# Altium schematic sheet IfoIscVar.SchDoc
size A; DocumentNumber: 3; SheetNumber: 3; SheetTotal: 11; pInstance: Corner
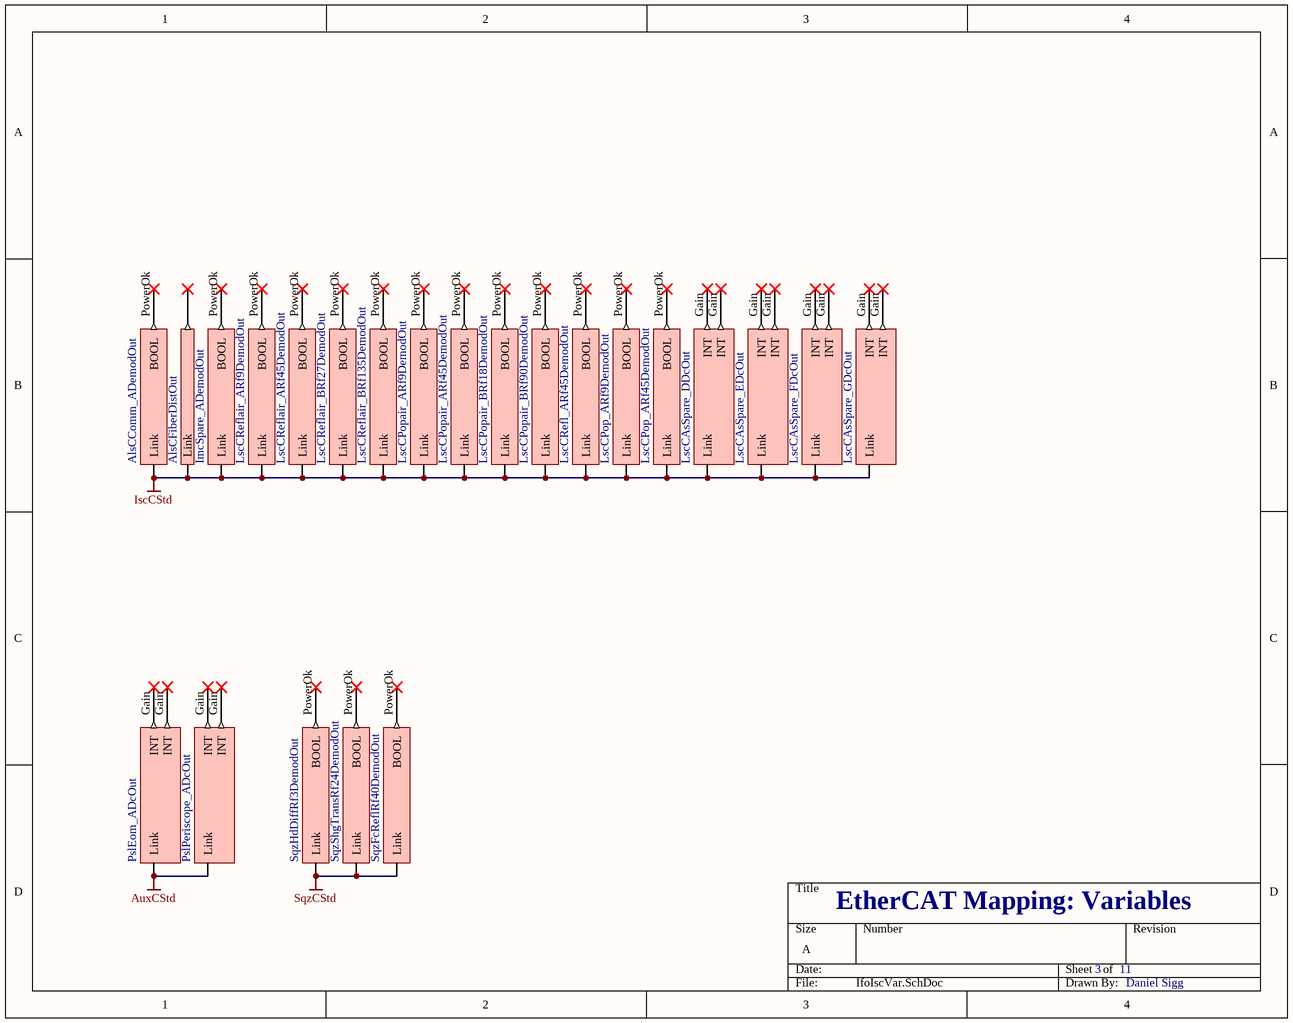
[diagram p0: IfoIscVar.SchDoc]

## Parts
V32  PslEom_ADcOut  (no BOM)
V33  PslPeriscope_ADcOut  (no BOM)
V34  AlsCComm_ADemodOut  (no BOM)
V35  AlsCFiberDistOut  (no BOM)
V36  ImcSpare_ADemodOut  (no BOM)
V37  LscCReflair_ARf9DemodOut  (no BOM)
V38  LscCReflair_ARf45DemodOut  (no BOM)
V39  LscCReflair_BRf27DemodOut  (no BOM)
V40  LscCReflair_BRf135DemodOut  (no BOM)
V41  LscCPopair_ARf9DemodOut  (no BOM)
V42  LscCPopair_ARf45DemodOut  (no BOM)
V43  LscCPopair_BRf18DemodOut  (no BOM)
V44  LscCPopair_BRf90DemodOut  (no BOM)
V45  LscCRefl_ARf45DemodOut  (no BOM)
V46  LscCPop_ARf9DemodOut  (no BOM)
V47  LscCPop_ARf45DemodOut  (no BOM)
V78  SqzHdDiffRf3DemodOut  (no BOM)
V79  SqzShgTransRf24DemodOut  (no BOM)
V80  SqzFcReflRf40DemodOut  (no BOM)
V740  LscCAsSpare_EDcOut  (no BOM)
V741  LscCAsSpare_FDcOut  (no BOM)
V742  LscCAsSpare_GDcOut  (no BOM)
V743  LscCAsSpare_DDcOut  (no BOM)

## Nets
AuxCStd: V32.0(Link) V33.0(Link)
IscCStd: V34.?1(Link) V35.?2(Link) V36.?1(Link) V37.?1(Link) V38.?1(Link) V39.?1(Link) V40.?1(Link) V41.?1(Link) V42.?1(Link) V43.?1(Link) V44.?1(Link) V45.?1(Link) V46.?1(Link) V47.?1(Link) V740.0(Link) V741.0(Link) V742.0(Link) V743.0(Link)
SqzCStd: V78.?1(Link) V79.?1(Link) V80.?1(Link)

Not connected (* = marked no-connect by the designer): V32 Gain(INT)*; V33 Gain(INT)*; V34 PowerOk(BOOL)*; V35 ?1*; V36 PowerOk(BOOL)*; V37 PowerOk(BOOL)*; V38 PowerOk(BOOL)*; V39 PowerOk(BOOL)*; V40 PowerOk(BOOL)*; V41 PowerOk(BOOL)*; V42 PowerOk(BOOL)*; V43 PowerOk(BOOL)*; V44 PowerOk(BOOL)*; V45 PowerOk(BOOL)*; V46 PowerOk(BOOL)*; V47 PowerOk(BOOL)*; V78 PowerOk(BOOL)*; V79 PowerOk(BOOL)*; V80 PowerOk(BOOL)*; V740 Gain(INT)*; V741 Gain(INT)*; V742 Gain(INT)*; V743 Gain(INT)*

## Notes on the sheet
- EtherCAT Mapping: Variables
- Daniel Sigg

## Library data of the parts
V32 V33 = DCPower_DCPowerOutStruct: DCPowerOutStruct; BoxType: Variable; Instance: H1AuxCorner Instance; PLC: H1AuxCorner; Task: AuxCStd
V34 V36-V47 = Demodulator_DemodulatorOutStruct: DemodulatorOutStruct; BoxType: Variable; Instance: H1IscCorner Instance; PLC: H1IscCorner; Task: IscCStd
V35 = VariableOut: FiberDistributionOutStruct; Instance: H1IscCorner Instance; PLC: H1IscCorner; Task: IscCStd
V78-V80 = Demodulator_DemodulatorOutStruct: DemodulatorOutStruct; BoxType: Variable; Instance: H1SqzCorner Instance; PLC: H1SqzCorner; Task: SqzCStd
V740-V743 = DCPower_DCPowerOutStruct: DCPowerOutStruct; BoxType: Variable; Instance: H1IscCorner Instance; PLC: H1IscCorner; Task: IscCStd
